Omron CX-Programmer project NuevoProyecto (CX-Programmer 9.50)

# PLC NewPLC1: CP1L-E EM

## Program P4 (cyclic task 0)
Local symbols
AN_retroceso 100.03 BOOL
A_avance 100.02 BOOL
CNT_igual_1 15.01 BOOL
CNT_igual_2 15.02 BOOL
Etapa_0 10.00 BOOL
Etapa_1 10.01 BOOL
Etapa_2 10.02 BOOL
Etapa_3 10.03 BOOL
Etapa_4 10.04 BOOL
Etapa_5 10.05 BOOL
Etapa_6 10.06 BOOL
F1 0.02 BOOL
F2 0.03 BOOL
F3 0.04 BOOL
F4 0.05 BOOL
FSF1 15.00 BOOL
M1 100.00 BOOL
M2 100.01 BOOL
PE 0.01 BOOL
m 0.00 BOOL

### Section Sección1_Programa_principal
; Programa principal (Etapas 0 ... 6)

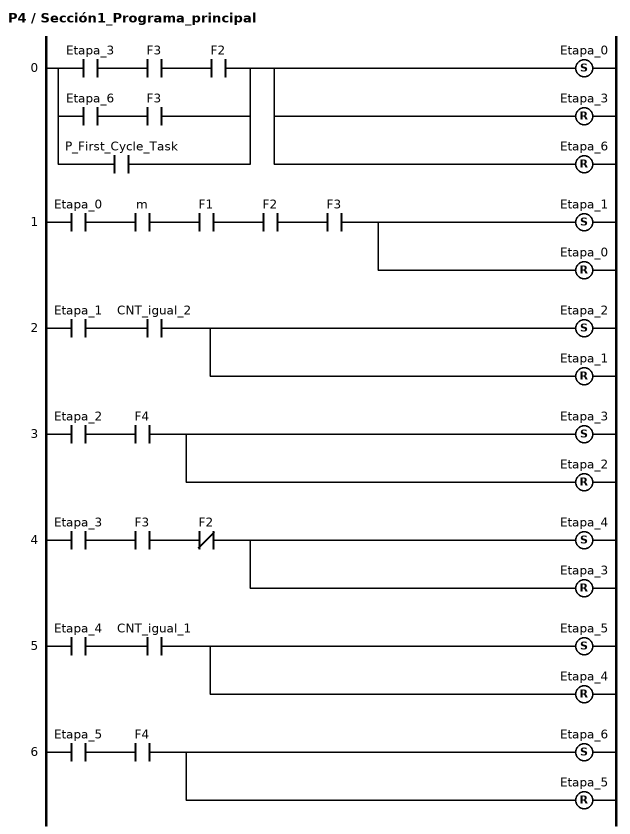
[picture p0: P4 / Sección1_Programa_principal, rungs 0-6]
; rung 0
LD Etapa_3
AND F3
AND F2
LD Etapa_6
AND F3
ORLD
OR P_First_Cycle_Task
SET Etapa_0
RSET Etapa_3
RSET Etapa_6
; rung 1
LD Etapa_0
AND m
AND F1
AND F2
AND F3
SET Etapa_1
RSET Etapa_0
; rung 2
LD Etapa_1
AND CNT_igual_2
SET Etapa_2
RSET Etapa_1
; rung 3
LD Etapa_2
AND F4
SET Etapa_3
RSET Etapa_2
; rung 4
LD Etapa_3
AND F3
ANDNOT F2
SET Etapa_4
RSET Etapa_3
; rung 5
LD Etapa_4
AND CNT_igual_1
SET Etapa_5
RSET Etapa_4
; rung 6
LD Etapa_5
AND F4
SET Etapa_6
RSET Etapa_5

### Section Sección2_FSF1_y_contador

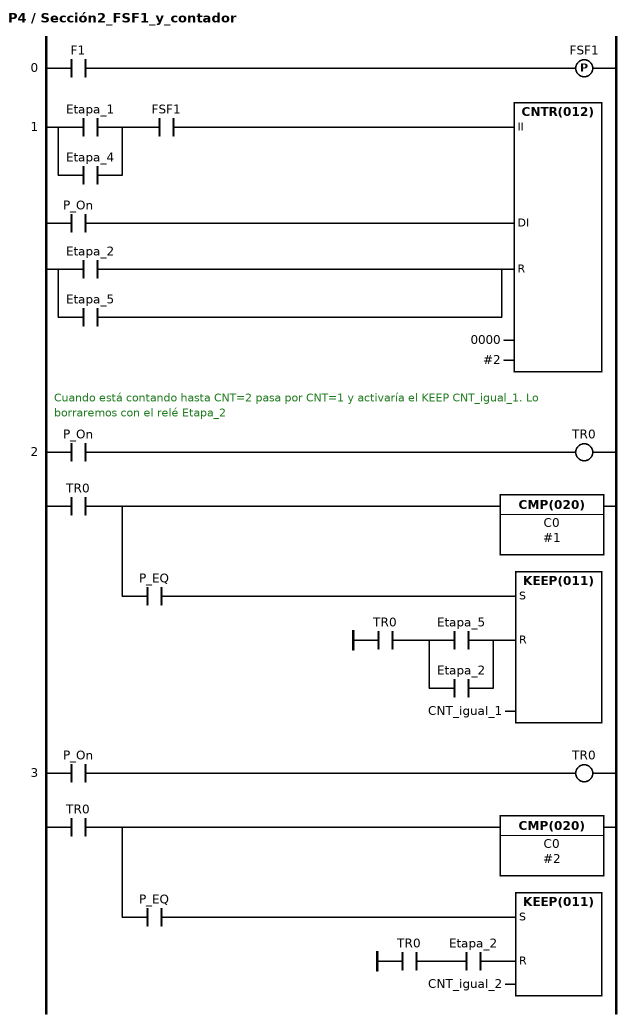
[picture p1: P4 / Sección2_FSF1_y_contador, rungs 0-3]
; rung 0
LD F1
DIFU(013) FSF1
; rung 1
LD Etapa_1
OR Etapa_4
AND FSF1
LD P_On
LD Etapa_2
OR Etapa_5
CNTR(012) 0000 #2
; rung 2: Cuando está contando hasta CNT=2 pasa por CNT=1 y activaría el KEEP CNT_igual_1. Lo borraremos con el relé Etapa_2
LD P_On
OUT TR0
CMP(020) C0 #1
AND P_EQ
LD TR0
LD Etapa_5
OR Etapa_2
ANDLD
KEEP(011) CNT_igual_1
; rung 3
LD P_On
OUT TR0
CMP(020) C0 #2
AND P_EQ
LD TR0
AND Etapa_2
KEEP(011) CNT_igual_2

### Section Sección3_Salidas

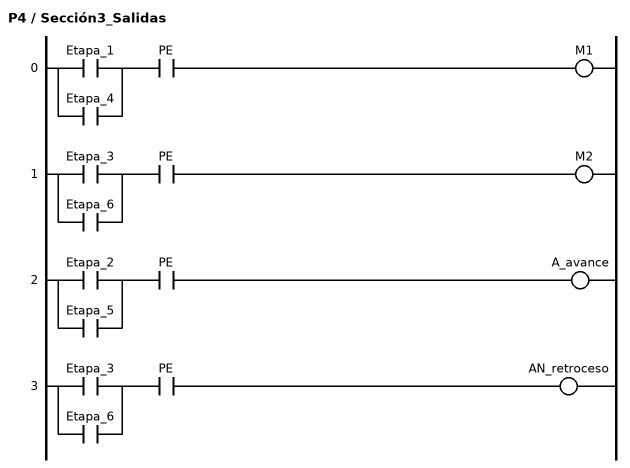
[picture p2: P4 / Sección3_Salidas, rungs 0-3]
; rung 0
LD Etapa_1
OR Etapa_4
AND PE
OUT M1
; rung 1
LD Etapa_3
OR Etapa_6
AND PE
OUT M2
; rung 2
LD Etapa_2
OR Etapa_5
AND PE
OUT A_avance
; rung 3
LD Etapa_3
OR Etapa_6
AND PE
OUT AN_retroceso

### Section Sección4_END
; rung 0: Fin de programa
END(001)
